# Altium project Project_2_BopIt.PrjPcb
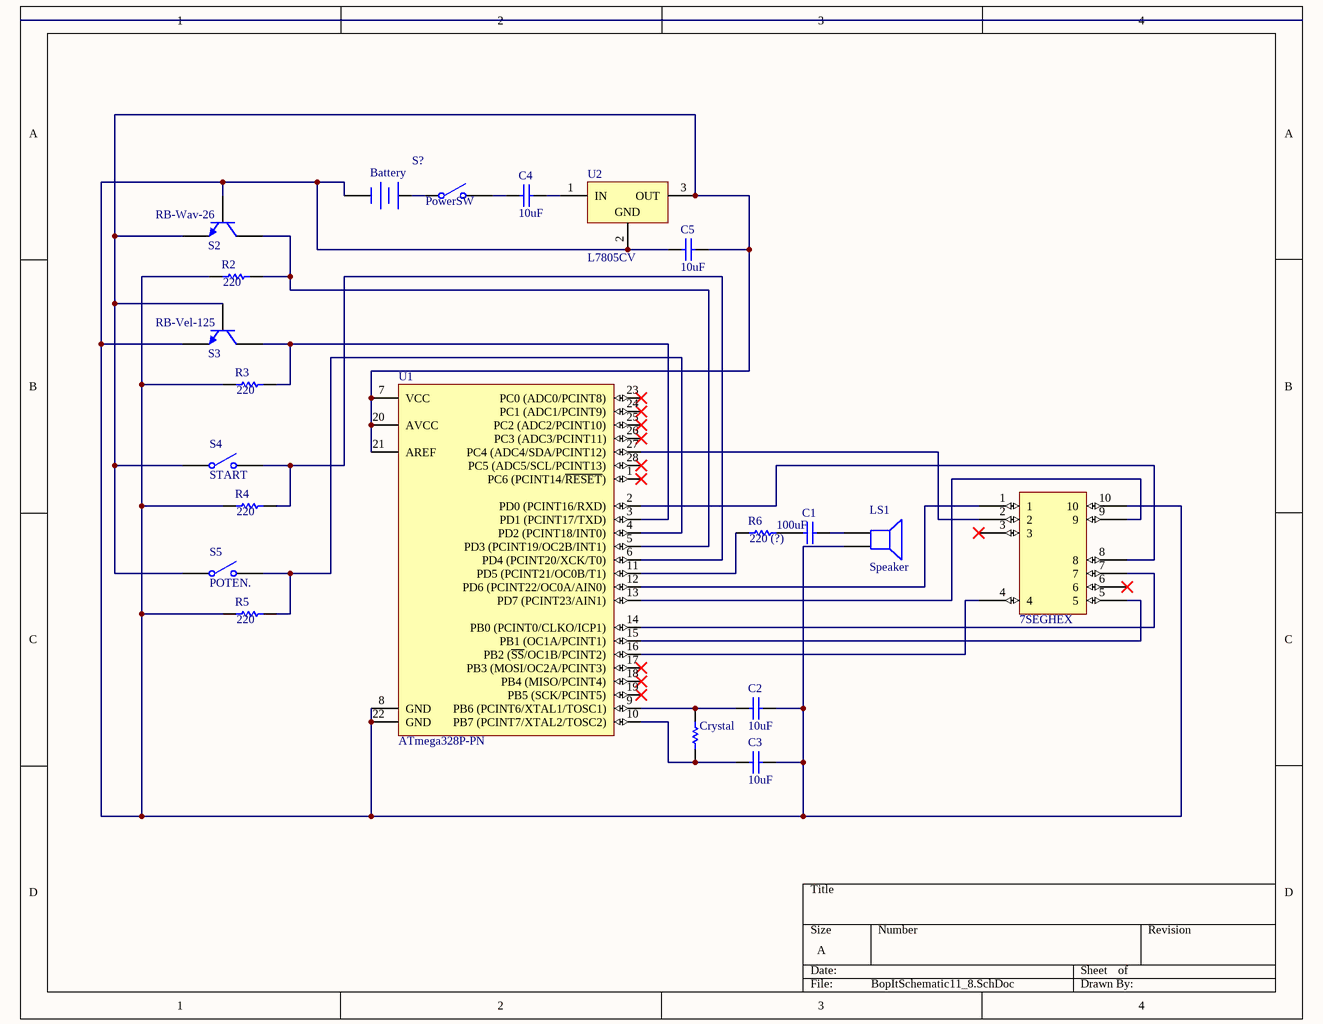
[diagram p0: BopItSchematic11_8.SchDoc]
1 sheet, 21 parts. Net scope: global (net labels, ports and power ports of the same name join across sheets).
Board file: Main11_8.PcbDoc

## Sheet BopItSchematic11_8.SchDoc
size A

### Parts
7SEGHEX  7SEGHEX  [7SEGHEX]  (value not drawn)
Battery  (no value)  [BAT-2]
C1  value 100uF  [RAD-0.3]
C2  10uF  [RAD-0.3]
C3  10uF  [RAD-0.3]
C4  value 10uF  [RAD-0.3]
C5  value 10uF  [RAD-0.3]
Crystal  (no value)  [AXIAL-0.3]
LS1  Speaker  [PIN2]
POW  PowerSW  [SPST-2]
R2  value 220  [AXIAL-0.3]
R3  value 220  [AXIAL-0.3]
R4  value 220  [AXIAL-0.3]
R5  value 220  [AXIAL-0.3]
R6  value 220 (?)  [AXIAL-0.3]
S2  RB-Wav-26  [TO-226-AA]
S3  RB-Vel-125  [TO-226-AA]
S4  START  [SPST-2]
S5  POTEN.  [SPST-2]
U1  ATmega328P-PN  [28P3]
U2  L7805CV  [TO220]

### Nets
Net7SEGHEX_1: 7SEGHEX.1 U1.12(PD6_(PCINT22/OC0A/AIN0))
Net7SEGHEX_2: 7SEGHEX.2 U1.27(PC4_(ADC4/SDA/PCINT12))
Net7SEGHEX_4: 7SEGHEX.4 U1.16(PB2_(~{SS}/OC1B/PCINT2))
Net7SEGHEX_5: 7SEGHEX.5 U1.15(PB1_(OC1A/PCINT1))
Net7SEGHEX_7: 7SEGHEX.7 U1.14(PB0_(PCINT0/CLKO/ICP1))
Net7SEGHEX_8: 7SEGHEX.8 U1.2(PD0_(PCINT16/RXD))
Net7SEGHEX_9: 7SEGHEX.9 U1.13(PD7_(PCINT23/AIN1))
Net7SEGHEX_10: 7SEGHEX.10 Battery.2(-) C2.2 C3.2 C5.2 LS1.2 R2.1 R3.1 R4.1 R5.1 S2.2(B) S3.3(E) U1.8(GND) U1.22(GND) U2.2(GND)
NetBattery_1: Battery.1(+) POW.1(COMMON)
NetC1_1: C1.1 R6.2
NetC1_2: C1.2 LS1.1
NetC2_1: C2.1 Crystal.2 U1.9(PB6_(PCINT6/XTAL1/TOSC1))
NetC3_1: C3.1 Crystal.1 U1.10(PB7_(PCINT7/XTAL2/TOSC2))
NetC4_1: C4.1 U2.1(IN)
NetC4_2: C4.2 POW.2(NO)
NetC5_1: C5.1 S2.3(E) S3.2(B) S4.1(COMMON) S5.1(COMMON) U1.7(VCC) U1.20(AVCC) U1.21(AREF) U2.3(OUT)
NetR2_2: R2.2 S2.1(C) U1.5(PD3_(PCINT19/OC2B/INT1))
NetR3_2: R3.2 S3.1(C) U1.3(PD1_(PCINT17/TXD))
NetR4_2: R4.2 S4.2(NO) U1.6(PD4_(PCINT20/XCK/T0))
NetR5_2: R5.2 S5.2(NO) U1.4(PD2_(PCINT18/INT0))
NetR6_1: R6.1 U1.11(PD5_(PCINT21/OC0B/T1))

Not connected (* = marked no-connect by the designer): 7SEGHEX 3* 6*; U1 1(PC6_(PCINT14/~{RESET}))* 17(PB3_(MOSI/OC2A/PCINT3))* 18(PB4_(MISO/PCINT4))* 19(PB5_(SCK/PCINT5))* 23(PC0_(ADC0/PCINT8))* 24(PC1_(ADC1/PCINT9))* 25(PC2_(ADC2/PCINT10))* 26(PC3_(ADC3/PCINT11))* 28(PC5_(ADC5/SCL/PCINT13))*

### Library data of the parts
7SEGHEX = 7SEGHEX: 7 segment Hex display
Battery = Battery: Multicell Battery
C1 C4 C5 = Cap: Capacitor
C2 C3 = Cap: Capacitor; Value: 100uF
Crystal = Res1: Resistor; Value: 220
LS1 = Speaker: Loudspeaker
POW S4 S5 = SW-SPST: Single-Pole, Single-Throw Switch
R2-R6 = Res1: Resistor
S2 S3 = NPN: Mic
U1 = CMP-0095-00355-1: 8-bit AVR Microcontroller, 32KB Flash, 1KB EEPROM, 2KB SRAM, 28-pin PDIP, Industrial Grade (-40°C to 105°C)
U2 = CMP-0244-00483-1: Positive Voltage Regulator, 5V, 3-Pin TO-220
